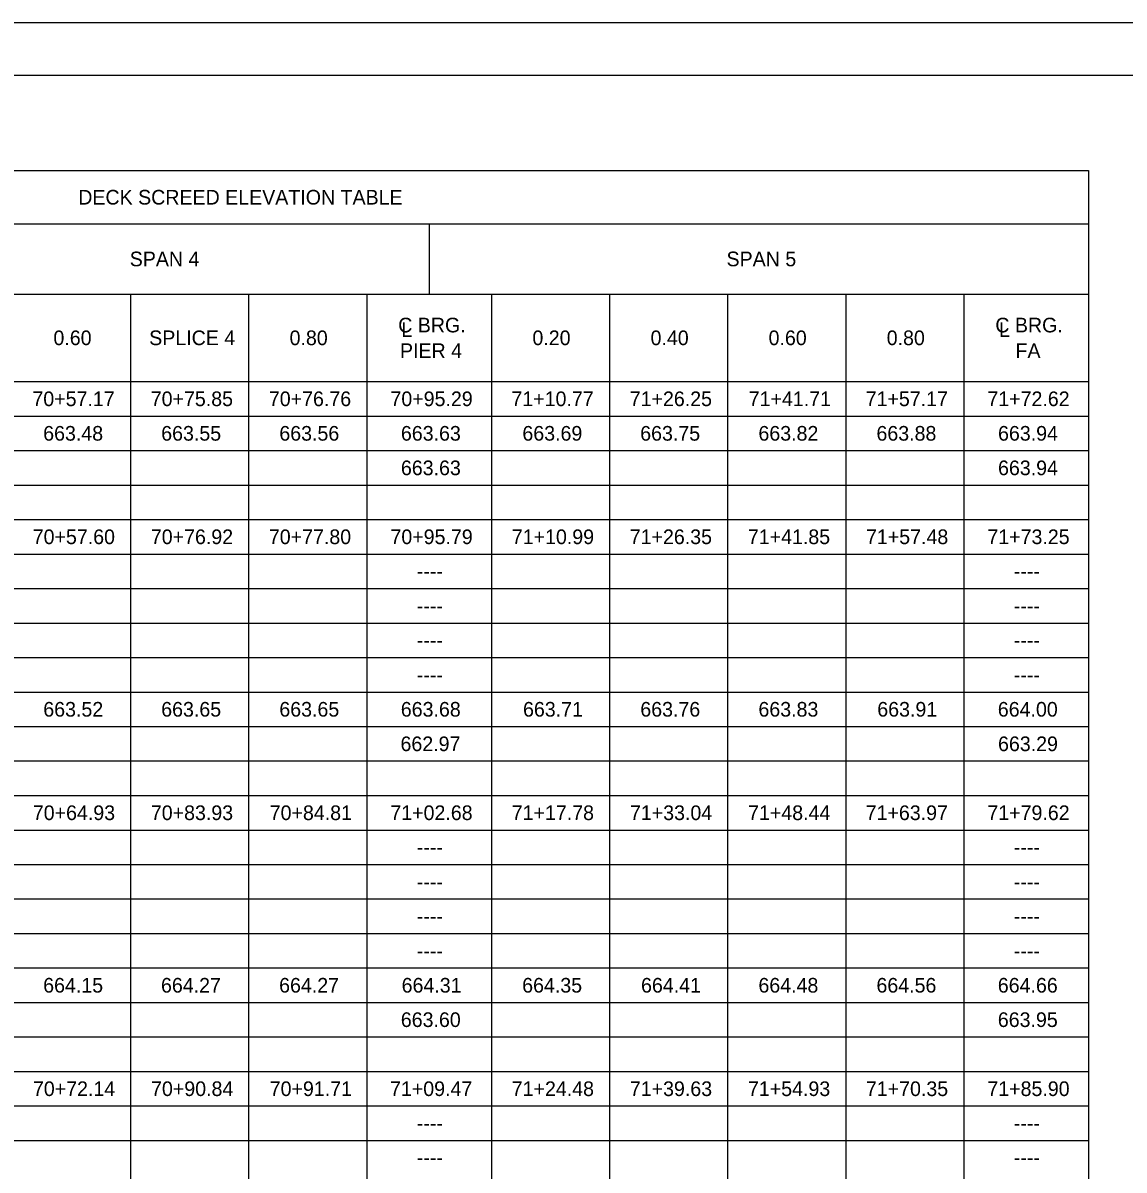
# Model space of a CAD drawing. Extents: x 0 to 34, y 0 to 22.
# Drawn here: x 9.87 to 20.39, y 11.03 to 22 of the extents above; entities that cross this region are included whole.
import ezdxf

# ---------------------------------------------------------------- set-up
doc = ezdxf.new("R2010")
doc.units = 0
for name, color, linetype in [('SH_Border', 7, 'Continuous'), ('SH_Cut_Line', 7, 'Continuous'), ('SH_Text', 7, 'Continuous')]:
    doc.layers.add(name, color=color, linetype=linetype)

msp = doc.modelspace()

# ---------------------------------------------------------------- linework, layer by layer
at = {"layer": 'SH_Border'}
msp.add_lwpolyline([(1.5, 21.5), (33.5, 21.5), (33.5, 0.5), (1.5, 0.5)], close=True, dxfattribs=at)
at = {"layer": 'SH_Cut_Line'}
msp.add_lwpolyline([(0, 0), (34, 0), (34, 22), (0, 22)], close=True, dxfattribs=at)
at = {"layer": 'SH_Text'}
for p, q in [((3.627, 20.588), (20.049, 20.588)), ((20.049, 20.588), (20.049, 1.756)), ((3.627, 20.08), (20.049, 20.08)), ((13.747, 20.08), (13.747, 19.408)), ((3.627, 19.408), (20.049, 19.408)), ((10.894, 19.408), (10.894, 1.756)), ((12.022, 19.408), (12.022, 1.756)), ((13.151, 19.408), (13.151, 1.756)), ((14.343, 19.408), (14.343, 1.756)), ((15.471, 19.408), (15.471, 1.756)), ((16.6, 19.408), (16.6, 1.756)), ((17.729, 19.408), (17.729, 1.756)), ((18.857, 19.408), (18.857, 1.756)), ((3.627, 18.571), (20.049, 18.571)), ((5.022, 18.242), (20.049, 18.242)), ((5.022, 17.912), (20.049, 17.912)), ((3.627, 17.582), (20.049, 17.582)), ((3.627, 17.253), (20.049, 17.253)), ((5.022, 16.923), (20.049, 16.923)), ((5.022, 16.593), (20.049, 16.593)), ((5.022, 16.263), (20.049, 16.263)), ((5.022, 15.934), (20.049, 15.934)), ((5.022, 15.604), (20.049, 15.604)), ((5.022, 15.274), (20.049, 15.274)), ((3.627, 14.945), (20.049, 14.945)), ((3.627, 14.615), (20.049, 14.615)), ((5.022, 14.285), (20.049, 14.285)), ((5.022, 13.955), (20.049, 13.955)), ((5.022, 13.626), (20.049, 13.626)), ((5.022, 13.296), (20.049, 13.296)), ((5.022, 12.966), (20.049, 12.966)), ((5.022, 12.637), (20.049, 12.637)), ((3.627, 12.307), (20.049, 12.307)), ((3.627, 11.977), (20.049, 11.977)), ((5.022, 11.647), (20.049, 11.647)), ((5.022, 11.318), (20.049, 11.318))]:
    msp.add_line(p, q, dxfattribs=at)

# ---------------------------------------------------------------- texts
for s, p in [('DECK SCREED ELEVATION TABLE', (10.394, 20.264)), ('SPAN 4', (10.886, 19.674)), ('SPAN 5', (16.59, 19.674)), ('C BRG.         ', (13.452, 19.042)), ('L', (13.482, 18.998)), ('C BRG.         ', (19.159, 19.042)), ('L', (19.194, 18.998)), ('0.60', (10.157, 18.92)), ('SPLICE 4', (11.072, 18.92)), ('0.80', (12.414, 18.92)), ('0.20', (14.735, 18.92)), ('0.40', (15.864, 18.92)), ('0.60', (16.992, 18.92)), ('0.80', (18.121, 18.92)), ('PIER 4', (13.469, 18.797)), ('FA', (19.352, 18.797)), ('70+57.17', (9.956, 18.337)), ('70+75.85', (11.087, 18.337)), ('70+76.76', (12.216, 18.337)), ('70+95.29', (13.378, 18.337)), ('71+10.77', (14.534, 18.337)), ('71+26.25', (15.665, 18.337)), ('71+41.71', (16.802, 18.337)), ('71+57.17', (17.92, 18.337)), ('71+72.62', (19.083, 18.337)), ('663.48', (10.059, 18.007)), ('663.55', (11.187, 18.007)), ('663.56', (12.316, 18.007)), ('663.63', (13.478, 18.007)), ('663.69', (14.639, 18.007)), ('663.75', (15.765, 18.007)), ('663.82', (16.895, 18.007)), ('663.88', (18.023, 18.007)), ('663.94', (19.185, 18.007)), ('663.63', (13.478, 17.677)), ('663.94', (19.185, 17.677)), ('70+57.60', (9.959, 17.018)), ('70+76.92', (11.088, 17.018)), ('70+77.80', (12.216, 17.018)), ('70+95.79', (13.378, 17.018)), ('71+10.99', (14.538, 17.018)), ('71+26.35', (15.665, 17.018)), ('71+41.85', (16.794, 17.018)), ('71+57.48', (17.923, 17.018)), ('71+73.25', (19.083, 17.018)), ('----', (13.63, 16.688)), ('----', (19.336, 16.688)), ('----', (13.63, 16.358)), ('----', (19.336, 16.358)), ('----', (13.63, 16.029)), ('----', (19.336, 16.029)), ('----', (13.63, 15.699)), ('----', (19.336, 15.699)), ('663.52', (10.06, 15.369)), ('663.65', (11.187, 15.369)), ('663.65', (12.316, 15.369)), ('663.68', (13.477, 15.369)), ('663.71', (14.645, 15.369)), ('663.76', (15.766, 15.369)), ('663.83', (16.895, 15.369)), ('663.91', (18.031, 15.369)), ('664.00', (19.183, 15.369)), ('662.97', (13.474, 15.039)), ('663.29', (19.185, 15.039)), ('70+64.93', (9.96, 14.38)), ('70+83.93', (11.088, 14.38)), ('70+84.81', (12.224, 14.38)), ('71+02.68', (13.377, 14.38)), ('71+17.78', (14.537, 14.38)), ('71+33.04', (15.667, 14.38)), ('71+48.44', (16.796, 14.38)), ('71+63.97', (17.92, 14.38)), ('71+79.62', (19.083, 14.38)), ('----', (13.63, 14.05)), ('----', (19.336, 14.05)), ('----', (13.63, 13.721)), ('----', (19.336, 13.721)), ('----', (13.63, 13.391)), ('----', (19.336, 13.391)), ('----', (13.63, 13.061)), ('----', (19.336, 13.061)), ('664.15', (10.059, 12.731)), ('664.27', (11.185, 12.731)), ('664.27', (12.314, 12.731)), ('664.31', (13.485, 12.731)), ('664.35', (14.637, 12.731)), ('664.41', (15.773, 12.731)), ('664.48', (16.895, 12.731)), ('664.56', (18.023, 12.731)), ('664.66', (19.183, 12.731)), ('663.60', (13.477, 12.402)), ('663.95', (19.183, 12.402)), ('70+72.14', (9.961, 11.742)), ('70+90.84', (11.09, 11.742)), ('70+91.71', (12.224, 11.742)), ('71+09.47', (13.374, 11.742)), ('71+24.48', (14.537, 11.742)), ('71+39.63', (15.666, 11.742)), ('71+54.93', (16.795, 11.742)), ('71+70.35', (17.922, 11.742)), ('71+85.90', (19.083, 11.742)), ('----', (13.63, 11.413)), ('----', (19.336, 11.413)), ('----', (13.63, 11.083)), ('----', (19.336, 11.083))]:
    msp.add_text(s, height=0.14, dxfattribs=at).set_placement(p)

doc.saveas('drawing.dxf')
